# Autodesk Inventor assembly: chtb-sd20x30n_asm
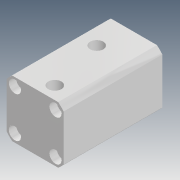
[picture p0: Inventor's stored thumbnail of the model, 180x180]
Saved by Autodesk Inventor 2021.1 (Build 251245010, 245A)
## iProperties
Company: Microsoft
Created: 2018-04
Part Number: chtb-sd20x30n_asm
Description: STEP AP214
Document SubType Name: Assembly
Designer: user
Title: chtb-sd20x30n_asm.STEP
Author: Windows
Revision Number: ÈÎºÎ
Sending System: SolidWorks 2015
Preprocessor: SwSTEP 2.0
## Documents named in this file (4)
- D:\Vault_2016\Projekty\Clamptek\Hydraulic\CHTB\CHTB-20\Inventor\CHTB-SD20x30N\chtb-sd20x30n_asm.iam
- D:\Vault_2016\Projekty\Clamptek\Hydraulic\CHTB\CHTB-20\Inventor\CHTB-SD20x30N\CHTB-SD20X30NBT.ipt
- D:\Vault_2016\Projekty\Clamptek\Hydraulic\CHTB\CHTB-20\Inventor\CHTB-SD20x30N\CHTB-SD20X30NHSG.ipt
- D:\Vault_2016\Projekty\Clamptek\Hydraulic\CHTB\CHTB-20\Inventor\CHTB-SD20x30N\QG.ipt
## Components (3 placed, 3 different names)
1. CHTB-SD20X30NBT_1
2. CHTB-SD20X30NHSG_2
3. QG_3
